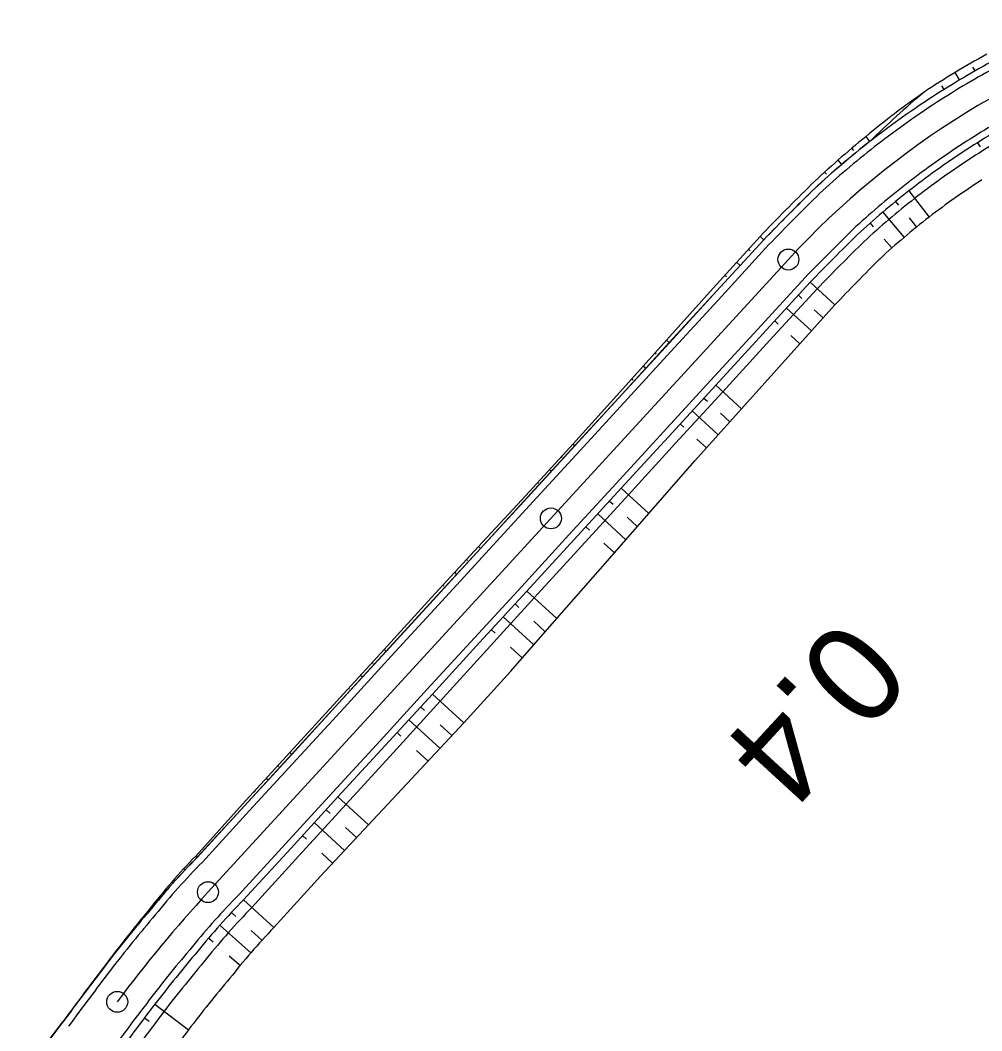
# Model space of a CAD drawing. Extents: x -481656 to -478728, y -1113199 to -1110710.
# Drawn here: x -479677.3 to -479608.4, y -1111510 to -1111437.6 of the extents above; entities that cross this region are included whole.
import ezdxf

# ---------------------------------------------------------------- set-up
doc = ezdxf.new("R2010")
doc.units = 0
for name, color, linetype in [('C5_HATCH_SLOPE_L', 7, 'Continuous'), ('C5_HATCH_SLOPE_R', 7, 'Continuous'), ('C5_HECTOMETRY', 7, 'Continuous'), ('C5_HLBODY', 7, 'Continuous'), ('C5_HRANA_TELESO', 7, 'Continuous'), ('C5_KORUNA', 7, 'Continuous'), ('C5_OSA', 7, 'Continuous'), ('C5_PRIKOP', 7, 'Continuous'), ('C5_ZPEVKRAJ', 7, 'Continuous')]:
    doc.layers.add(name, color=color, linetype=linetype)

msp = doc.modelspace()

# ---------------------------------------------------------------- linework, layer by layer
at = {"layer": 'C5_HATCH_SLOPE_L'}
for p, q in [((-479609.227, -1111440.699), (-479609.227, -1111440.699)), ((-479608.916, -1111441.245), (-479609.072, -1111440.972)), ((-479610.035, -1111441.899), (-479610.355, -1111441.365)), ((-479611.469, -1111442.054), (-479611.469, -1111442.054)), ((-479611.141, -1111442.577), (-479611.305, -1111442.316)), ((-479616.445, -1111446.302), (-479616.726, -1111445.943)), ((-479617.598, -1111446.94), (-479617.733, -1111446.775)), ((-479618.454, -1111447.943), (-479618.722, -1111447.628)), ((-479617.458, -1111447.112), (-479617.461, -1111447.108)), ((-479619.566, -1111448.644), (-479619.693, -1111448.501)), ((-479619.432, -1111448.794), (-479619.435, -1111448.79)), ((-479624.041, -1111453.343), (-479624.312, -1111453.094)), ((-479625.022, -1111454.14), (-479625.15, -1111454.022)), ((-479624.886, -1111454.265), (-479624.89, -1111454.262)), ((-479625.731, -1111455.186), (-479625.988, -1111454.95)), ((-479626.704, -1111455.989), (-479626.825, -1111455.878)), ((-479626.576, -1111456.107), (-479626.58, -1111456.104)), ((-479630.801, -1111460.713), (-479631.009, -1111460.522)), ((-479631.748, -1111461.54), (-479631.842, -1111461.454)), ((-479631.645, -1111461.634), (-479631.649, -1111461.63)), ((-479632.49, -1111462.555), (-479632.675, -1111462.386)), ((-479633.425, -1111463.394), (-479633.507, -1111463.318)), ((-479633.335, -1111463.476), (-479633.339, -1111463.472)), ((-479637.56, -1111468.082), (-479637.7, -1111467.954)), ((-479638.478, -1111468.936), (-479638.544, -1111468.876)), ((-479638.405, -1111469.003), (-479638.409, -1111469)), ((-479639.25, -1111469.924), (-479639.388, -1111469.798)), ((-479640.168, -1111470.779), (-479640.233, -1111470.719)), ((-479640.095, -1111470.845), (-479640.099, -1111470.842)), ((-479644.32, -1111475.451), (-479644.474, -1111475.31)), ((-479645.246, -1111476.298), (-479645.321, -1111476.229)), ((-479645.165, -1111476.372), (-479645.168, -1111476.369)), ((-479646.01, -1111477.294), (-479646.169, -1111477.148)), ((-479646.939, -1111478.138), (-479647.016, -1111478.067)), ((-479646.855, -1111478.215), (-479646.858, -1111478.212)), ((-479651.08, -1111482.82), (-479651.229, -1111482.684)), ((-479652.002, -1111483.67), (-479652.072, -1111483.606)), ((-479651.925, -1111483.742), (-479651.928, -1111483.738)), ((-479652.77, -1111484.663), (-479652.916, -1111484.528)), ((-479653.691, -1111485.514), (-479653.76, -1111485.45)), ((-479653.615, -1111485.584), (-479653.618, -1111485.58)), ((-479657.839, -1111490.19), (-479657.98, -1111490.061)), ((-479658.758, -1111491.044), (-479658.824, -1111490.983)), ((-479658.684, -1111491.111), (-479658.688, -1111491.108)), ((-479659.529, -1111492.032), (-479659.668, -1111491.905)), ((-479660.446, -1111492.886), (-479660.511, -1111492.827)), ((-479660.374, -1111492.953), (-479660.378, -1111492.95)), ((-479664.599, -1111497.559), (-479664.708, -1111497.46)), ((-479665.496, -1111498.432), (-479665.541, -1111498.392)), ((-479665.444, -1111498.48), (-479665.448, -1111498.476)), ((-479666.302, -1111499.426), (-479666.387, -1111499.349)), ((-479667.19, -1111500.347), (-479667.223, -1111500.318)), ((-479667.149, -1111500.383), (-479667.152, -1111500.38)), ((-479671.982, -1111506.335), (-479671.984, -1111506.334)), ((-479671.972, -1111506.342), (-479671.976, -1111506.339))]:
    msp.add_line(p, q, dxfattribs=at)
at = {"layer": 'C5_HATCH_SLOPE_R'}
for p, q in [((-479608.75, -1111446.389), (-479608.567, -1111446.68)), ((-479613.671, -1111449.845), (-479612.21, -1111451.711)), ((-479614.61, -1111450.596), (-479614.394, -1111450.862)), ((-479615.534, -1111451.367), (-479613.999, -1111453.168)), ((-479613.645, -1111451.778), (-479613.112, -1111452.43)), ((-479616.441, -1111452.157), (-479616.213, -1111452.413)), ((-479615.428, -1111453.296), (-479614.87, -1111453.924)), ((-479620.725, -1111456.385), (-479618.959, -1111458.005)), ((-479621.57, -1111457.306), (-479621.318, -1111457.537)), ((-479622.415, -1111458.228), (-479620.632, -1111459.862)), ((-479620.431, -1111458.351), (-479619.796, -1111458.934)), ((-479623.26, -1111459.149), (-479623.008, -1111459.379)), ((-479622.113, -1111460.2), (-479621.469, -1111460.791)), ((-479627.484, -1111463.755), (-479625.648, -1111465.439)), ((-479628.329, -1111464.676), (-479628.078, -1111464.906)), ((-479629.174, -1111465.597), (-479627.31, -1111467.307)), ((-479627.153, -1111465.754), (-479626.479, -1111466.373)), ((-479630.019, -1111466.518), (-479629.767, -1111466.749)), ((-479628.828, -1111467.61), (-479628.141, -1111468.241)), ((-479634.244, -1111471.124), (-479632.278, -1111472.928)), ((-479635.089, -1111472.045), (-479634.832, -1111472.28)), ((-479635.934, -1111472.966), (-479633.916, -1111474.817)), ((-479633.836, -1111473.194), (-479633.097, -1111473.872)), ((-479636.779, -1111473.887), (-479636.519, -1111474.125)), ((-479635.498, -1111475.062), (-479634.736, -1111475.762)), ((-479641.004, -1111478.493), (-479638.855, -1111480.464)), ((-479641.849, -1111479.414), (-479641.582, -1111479.66)), ((-479642.694, -1111480.335), (-479640.509, -1111482.339)), ((-479640.498, -1111480.654), (-479639.682, -1111481.402)), ((-479643.539, -1111481.257), (-479643.268, -1111481.504)), ((-479642.167, -1111482.514), (-479641.336, -1111483.277)), ((-479647.764, -1111485.862), (-479645.509, -1111487.931)), ((-479648.609, -1111486.783), (-479648.33, -1111487.038)), ((-479649.454, -1111487.705), (-479647.219, -1111489.755)), ((-479647.208, -1111488.068), (-479646.364, -1111488.843)), ((-479650.298, -1111488.626), (-479650.017, -1111488.884)), ((-479648.905, -1111489.904), (-479648.074, -1111490.667)), ((-479654.523, -1111493.232), (-479652.348, -1111495.227)), ((-479655.368, -1111494.153), (-479655.079, -1111494.418)), ((-479656.213, -1111495.074), (-479654.054, -1111497.055)), ((-479653.996, -1111495.412), (-479653.201, -1111496.141)), ((-479657.058, -1111495.995), (-479656.766, -1111496.263)), ((-479655.69, -1111497.25), (-479654.906, -1111497.969)), ((-479661.283, -1111500.601), (-479659.117, -1111502.588)), ((-479662.128, -1111501.522), (-479661.828, -1111501.798)), ((-479662.95, -1111502.428), (-479660.736, -1111504.411)), ((-479663.759, -1111503.343), (-479663.45, -1111503.614)), ((-479660.739, -1111502.796), (-479659.95, -1111503.52)), ((-479662.324, -1111504.597), (-479661.508, -1111505.31)), ((-479667.632, -1111508.067), (-479665.235, -1111509.911)), ((-479668.371, -1111509.04), (-479668.033, -1111509.294))]:
    msp.add_line(p, q, dxfattribs=at)
at = {"layer": 'C5_HECTOMETRY'}
msp.add_circle((-479639.282, -1111473.288), 0.75, dxfattribs=at)
msp.add_circle((-479639.282, -1111473.288), 0.75, dxfattribs=at)
at = {"layer": 'C5_HLBODY'}
for centre in [(-479622.283, -1111454.755), (-479622.283, -1111454.755), (-479663.832, -1111500.051), (-479663.832, -1111500.051), (-479670.328, -1111507.901)]:
    msp.add_circle(centre, 0.75, dxfattribs=at)
at = {"layer": 'C5_HRANA_TELESO'}
for p, q in [((-479627.663, -1111456.806), (-479624.312, -1111453.094)), ((-479631.009, -1111460.522), (-479627.663, -1111456.806)), ((-479622.306, -1111461.72), (-479618.959, -1111458.005)), ((-479634.34, -1111464.251), (-479631.009, -1111460.522)), ((-479625.648, -1111465.439), (-479622.306, -1111461.72)), ((-479637.7, -1111467.954), (-479634.34, -1111464.251)), ((-479628.971, -1111469.175), (-479625.648, -1111465.439)), ((-479641.077, -1111471.641), (-479637.7, -1111467.954)), ((-479632.278, -1111472.928), (-479628.971, -1111469.175)), ((-479644.474, -1111475.31), (-479641.077, -1111471.641)), ((-479635.555, -1111476.706), (-479632.278, -1111472.928)), ((-479647.864, -1111478.985), (-479644.474, -1111475.31)), ((-479638.855, -1111480.464), (-479635.555, -1111476.706)), ((-479651.229, -1111482.684), (-479647.864, -1111478.985)), ((-479642.163, -1111484.215), (-479638.855, -1111480.464)), ((-479654.604, -1111486.372), (-479651.229, -1111482.684)), ((-479645.509, -1111487.931), (-479642.163, -1111484.215)), ((-479657.98, -1111490.061), (-479654.604, -1111486.372)), ((-479648.929, -1111491.579), (-479645.509, -1111487.931)), ((-479661.355, -1111493.75), (-479657.98, -1111490.061)), ((-479652.348, -1111495.227), (-479648.929, -1111491.579)), ((-479664.708, -1111497.46), (-479661.355, -1111493.75)), ((-479655.759, -1111498.883), (-479652.348, -1111495.227)), ((-479659.117, -1111502.588), (-479655.759, -1111498.883)), ((-479677.27, -1111513.314), (-479674.229, -1111509.345))]:
    msp.add_line(p, q, dxfattribs=at)
for centre, radius, start, end in [((-479577.825, -1111495.168), 62.873, 118.76987, 123.54456), ((-479576.565, -1111494.201), 62.783, 124.99058, 129.76734), ((-479577.312, -1111494.659), 62.664, 128.97482, 133.75007), ((-479578.447, -1111495.584), 55.36, 122.80527, 127.58009), ((-479489.043, -1111583.463), 187.867, 134.46783, 136.05695), ((-479578.136, -1111495.372), 55.383, 127.96926, 132.74392), ((-479498.561, -1111572.521), 166.162, 134.83983, 136.43449), ((-479627.821, -1111532.919), 51.166, 136.13073, 141.82927), ((-479589.288, -1111566.582), 102.298, 140.34375, 143.20879), ((-479624.978, -1111535.432), 47.372, 136.10744, 141.9244), ((-479427.164, -1111691.226), 306.793, 142.70049, 143.64067), ((-479589.899, -1111567.351), 94.735, 139.81113, 142.67594), ((-479436.283, -1111678.249), 284.177, 143.67456, 144.6667)]:
    msp.add_arc(centre, radius, start, end, dxfattribs=at)
at = {"layer": 'C5_KORUNA'}
for p, q in [((-479627.421, -1111457.028), (-479624.041, -1111453.343)), ((-479624.104, -1111460.07), (-479620.725, -1111456.385)), ((-479630.801, -1111460.713), (-479627.421, -1111457.028)), ((-479627.484, -1111463.755), (-479624.104, -1111460.07)), ((-479634.18, -1111464.397), (-479630.801, -1111460.713)), ((-479637.56, -1111468.082), (-479634.18, -1111464.397)), ((-479630.864, -1111467.439), (-479627.484, -1111463.755)), ((-479634.244, -1111471.124), (-479630.864, -1111467.439)), ((-479640.94, -1111471.767), (-479637.56, -1111468.082)), ((-479637.624, -1111474.808), (-479634.244, -1111471.124)), ((-479644.32, -1111475.451), (-479640.94, -1111471.767)), ((-479641.004, -1111478.493), (-479637.624, -1111474.808)), ((-479647.7, -1111479.136), (-479644.32, -1111475.451)), ((-479644.384, -1111482.178), (-479641.004, -1111478.493)), ((-479651.08, -1111482.82), (-479647.7, -1111479.136)), ((-479647.764, -1111485.862), (-479644.384, -1111482.178)), ((-479654.46, -1111486.505), (-479651.08, -1111482.82)), ((-479651.143, -1111489.547), (-479647.764, -1111485.862)), ((-479657.839, -1111490.19), (-479654.46, -1111486.505)), ((-479654.523, -1111493.232), (-479651.143, -1111489.547)), ((-479661.219, -1111493.874), (-479657.839, -1111490.19)), ((-479657.903, -1111496.916), (-479654.523, -1111493.232)), ((-479664.599, -1111497.559), (-479661.219, -1111493.874)), ((-479661.283, -1111500.601), (-479657.903, -1111496.916))]:
    msp.add_line(p, q, dxfattribs=at)
for centre, radius, start, end in [((-479578.067, -1111495.314), 62.25, 118.51298, 123.28763), ((-479578.067, -1111495.314), 62.25, 123.28763, 128.06227), ((-479578.067, -1111495.314), 57.75, 118.51297, 123.28762), ((-479578.067, -1111495.314), 62.25, 128.06227, 132.83692), ((-479578.067, -1111495.314), 57.75, 123.28762, 128.06227), ((-479489.671, -1111583.037), 186.75, 134.42502, 136.01446), ((-479578.067, -1111495.314), 57.75, 128.06227, 132.83691), ((-479496.054, -1111576.689), 173.25, 134.42825, 136.02122), ((-479628.195, -1111533.455), 51.125, 135.4026, 141.10088), ((-479626.507, -1111534.943), 48.875, 135.35936, 141.12569), ((-479590.139, -1111567.648), 102.25, 139.58019, 142.44498), ((-479590.139, -1111567.648), 97.75, 139.58019, 142.44498), ((-479427.163, -1111691.178), 306.75, 142.70782, 143.64809), ((-479434.369, -1111685.786), 293.25, 142.69693, 143.6672)]:
    msp.add_arc(centre, radius, start, end, dxfattribs=at)
at = {"layer": 'C5_OSA'}
msp.add_line((-479663.832, -1111500.051), (-479622.283, -1111454.755), dxfattribs=at)
for centre, radius, start, end in [((-479578.067, -1111495.314), 60, 105.93368, 137.47016), ((-479590.139, -1111567.648), 100, 137.47018, 143.31086)]:
    msp.add_arc(centre, radius, start, end, dxfattribs=at)
at = {"layer": 'C5_PRIKOP'}
for p, q in [((-479627.428, -1111457.021), (-479624.048, -1111453.337)), ((-479630.808, -1111460.706), (-479627.428, -1111457.021)), ((-479623.603, -1111460.53), (-479620.221, -1111456.847)), ((-479634.188, -1111464.391), (-479630.808, -1111460.706)), ((-479626.983, -1111464.215), (-479623.603, -1111460.53)), ((-479637.568, -1111468.075), (-479634.188, -1111464.391)), ((-479630.36, -1111467.902), (-479626.983, -1111464.215)), ((-479633.733, -1111471.593), (-479630.36, -1111467.902)), ((-479640.947, -1111471.76), (-479637.568, -1111468.075)), ((-479637.103, -1111475.287), (-479633.733, -1111471.593)), ((-479644.327, -1111475.444), (-479640.947, -1111471.76)), ((-479640.472, -1111478.981), (-479637.103, -1111475.287)), ((-479647.707, -1111479.129), (-479644.327, -1111475.444)), ((-479651.087, -1111482.814), (-479647.707, -1111479.129)), ((-479643.841, -1111482.676), (-479640.472, -1111478.981)), ((-479654.467, -1111486.498), (-479651.087, -1111482.814)), ((-479647.21, -1111486.37), (-479643.841, -1111482.676)), ((-479657.847, -1111490.183), (-479654.467, -1111486.498)), ((-479650.579, -1111490.065), (-479647.21, -1111486.37)), ((-479661.227, -1111493.868), (-479657.847, -1111490.183)), ((-479653.948, -1111493.76), (-479650.579, -1111490.065)), ((-479664.607, -1111497.552), (-479661.227, -1111493.868)), ((-479657.317, -1111497.454), (-479653.948, -1111493.76)), ((-479660.686, -1111501.149), (-479657.317, -1111497.454)), ((-479677.212, -1111513.357), (-479674.225, -1111509.348))]:
    msp.add_line(p, q, dxfattribs=at)
for centre, radius, start, end in [((-479572.483, -1111490.798), 62.561, 129.84664, 134.65292), ((-479578.084, -1111495.324), 57.061, 118.49276, 123.26741), ((-479578.067, -1111495.314), 62.26, 128.06227, 132.83692), ((-479578.084, -1111495.326), 57.063, 123.26722, 128.04187), ((-479489.657, -1111583.051), 186.78, 134.42502, 136.01445), ((-479578.082, -1111495.327), 57.065, 128.04206, 132.8167), ((-479497.068, -1111575.765), 171.197, 134.40859, 136.00218), ((-479628.199, -1111533.452), 51.13, 135.40269, 141.10083), ((-479590.139, -1111567.648), 102.26, 139.58019, 142.44498), ((-479626.106, -1111535.102), 48.462, 135.52424, 141.30399), ((-479589.954, -1111567.418), 96.917, 139.75479, 142.61959), ((-479435.19, -1111684.089), 290.729, 142.86561, 143.84179)]:
    msp.add_arc(centre, radius, start, end, dxfattribs=at)
at = {"layer": 'C5_ZPEVKRAJ'}
for p, q in [((-479627.052, -1111457.366), (-479623.672, -1111453.681)), ((-479624.473, -1111459.732), (-479621.093, -1111456.047)), ((-479630.432, -1111461.051), (-479627.052, -1111457.366)), ((-479627.853, -1111463.417), (-479624.473, -1111459.732)), ((-479633.812, -1111464.735), (-479630.432, -1111461.051)), ((-479631.233, -1111467.101), (-479627.853, -1111463.417)), ((-479637.192, -1111468.42), (-479633.812, -1111464.735)), ((-479634.613, -1111470.786), (-479631.233, -1111467.101)), ((-479640.572, -1111472.105), (-479637.192, -1111468.42)), ((-479637.992, -1111474.47), (-479634.613, -1111470.786)), ((-479643.952, -1111475.789), (-479640.572, -1111472.105)), ((-479641.372, -1111478.155), (-479637.992, -1111474.47)), ((-479647.331, -1111479.474), (-479643.952, -1111475.789)), ((-479644.752, -1111481.84), (-479641.372, -1111478.155)), ((-479650.711, -1111483.158), (-479647.331, -1111479.474)), ((-479648.132, -1111485.524), (-479644.752, -1111481.84)), ((-479654.091, -1111486.843), (-479650.711, -1111483.158)), ((-479651.512, -1111489.209), (-479648.132, -1111485.524)), ((-479657.471, -1111490.528), (-479654.091, -1111486.843)), ((-479654.892, -1111492.894), (-479651.512, -1111489.209)), ((-479660.851, -1111494.212), (-479657.471, -1111490.528)), ((-479658.272, -1111496.578), (-479654.892, -1111492.894)), ((-479664.231, -1111497.897), (-479660.851, -1111494.212)), ((-479661.652, -1111500.263), (-479658.272, -1111496.578))]:
    msp.add_line(p, q, dxfattribs=at)
for centre, radius, start, end in [((-479578.067, -1111495.314), 61.75, 118.51298, 123.28763), ((-479578.067, -1111495.314), 61.75, 123.28763, 128.06227), ((-479578.067, -1111495.314), 58.25, 118.51297, 123.28762), ((-479578.067, -1111495.314), 61.75, 128.06227, 132.83692), ((-479578.067, -1111495.314), 58.25, 123.28762, 128.06227), ((-479578.067, -1111495.314), 58.25, 128.06227, 132.83692), ((-479490.381, -1111582.332), 185.25, 134.42536, 136.01517), ((-479495.345, -1111577.394), 174.75, 134.42787, 136.02042), ((-479628.008, -1111533.62), 50.875, 135.39798, 141.10352), ((-479626.695, -1111534.778), 49.125, 135.36435, 141.12281), ((-479590.139, -1111567.648), 101.75, 139.58019, 142.44498), ((-479590.139, -1111567.648), 98.25, 139.58019, 142.44498), ((-479427.963, -1111690.579), 305.25, 142.70667, 143.65014), ((-479433.568, -1111686.385), 294.75, 142.6982, 143.665)]:
    msp.add_arc(centre, radius, start, end, dxfattribs=at)

# ---------------------------------------------------------------- texts
at = {"layer": 'C5_HECTOMETRY'}
msp.add_text('0.4', height=7, rotation=227.42454, dxfattribs=at).set_placement((-479618.426, -1111480.149))

doc.saveas('drawing.dxf')
